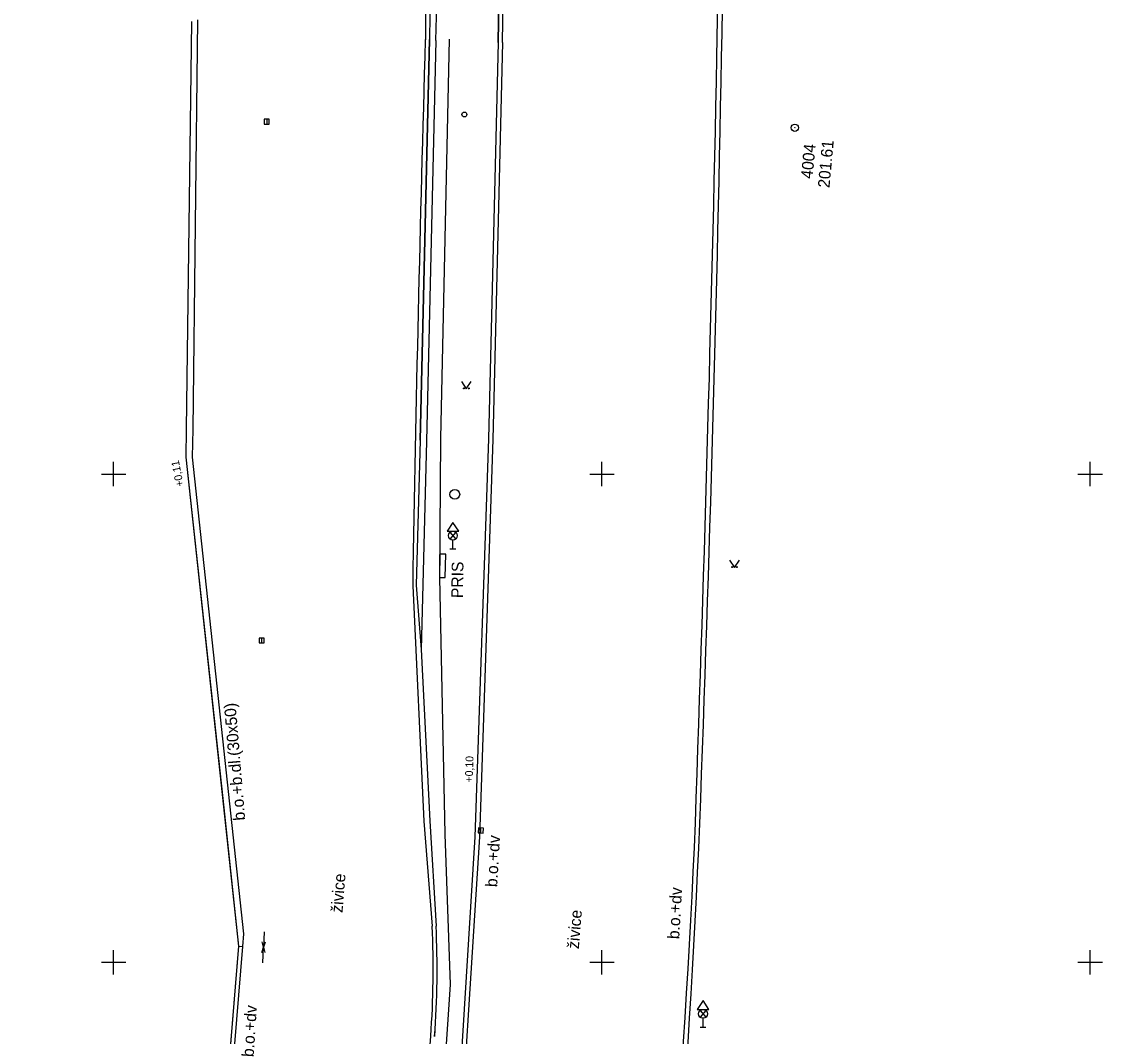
# Model space of a CAD drawing. Extents: x -599151 to -598424, y -1163476 to -1161924.
# Drawn here: x -598679.7 to -598624.4, y -1162503.8 to -1162451.8 of the extents above; entities that cross this region are included whole.
import ezdxf

# ---------------------------------------------------------------- set-up
doc = ezdxf.new("R2010")
doc.units = 0
for name, color, linetype in [('Vrstva 10', 7, 'Continuous'), ('Vrstva 14', 7, 'Continuous'), ('Vrstva 2', 7, 'Continuous'), ('Vrstva 21', 7, 'Continuous'), ('Vrstva 23', 7, 'Continuous'), ('Vrstva 25', 7, 'Continuous'), ('Vrstva 29', 7, 'Continuous'), ('Vrstva 44', 7, 'Continuous'), ('Vrstva 49', 7, 'Continuous'), ('Vrstva 50', 7, 'Continuous'), ('Vrstva 62', 7, 'Continuous'), ('Vrstva 63', 7, 'Continuous'), ('Vrstva 7', 7, 'Continuous')]:
    doc.layers.add(name, color=color, linetype=linetype)

msp = doc.modelspace()

# ---------------------------------------------------------------- linework, layer by layer
at = {"layer": 'Vrstva 10'}
msp.add_lwpolyline([(-598657.82, -1162452.73), (-598658.26, -1162473.18), (-598658.32, -1162480.293), (-598658.04, -1162493.44), (-598657.77, -1162501.13), (-598658.57, -1162513.12), (-598660.43, -1162532.68), (-598662.96, -1162552.16), (-598666.55, -1162571.73), (-598670.98, -1162591.44), (-598675.92, -1162611.16), (-598679.71, -1162624.76)], dxfattribs=at)
at = {"layer": 'Vrstva 14'}
for points in [[(-598657.193, -1162470.259), (-598656.943, -1162470.634), (-598656.693, -1162470.259)], [(-598643.462, -1162479.411), (-598643.212, -1162479.786), (-598642.962, -1162479.411)]]:
    msp.add_lwpolyline(points, dxfattribs=at)
for centre in [(-598657.068, -1162470.609), (-598656.818, -1162470.609), (-598643.337, -1162479.761), (-598643.087, -1162479.761)]:
    msp.add_circle(centre, 0.025, dxfattribs=at)
at = {"layer": 'Vrstva 2'}
for radius in [0.187, 0.00896]:
    msp.add_circle((-598640.12, -1162457.26), radius, dxfattribs=at)
at = {"layer": 'Vrstva 21'}
msp.add_lwpolyline([(-598658.5, -1162452.8), (-598658.98, -1162473.31), (-598659.26, -1162483.98), (-598658.81, -1162492.76), (-598658.491, -1162498.147)], dxfattribs=at)
for centre, radius, start, end in [((-601785.869, -1162380.888), 3128.195, 358.68275, 359.408531), ((-598705.141, -1162500.386), 46.704, 355.8125, 2.7473)]:
    msp.add_arc(centre, radius, start, end, dxfattribs=at)
at = {"layer": 'Vrstva 23'}
msp.add_circle((-598657.04, -1162456.58), 0.125, dxfattribs=at)
at = {"layer": 'Vrstva 25'}
for p, q in [((-598667.16, -1162456.825), (-598667.16, -1162457.075)), ((-598667.42, -1162483.395), (-598667.42, -1162483.645)), ((-598656.205, -1162493.375), (-598656.195, -1162493.125))]:
    msp.add_line(p, q, dxfattribs=at)
for points in [[(-598667.285, -1162456.825), (-598667.285, -1162457.075), (-598667.035, -1162457.075), (-598667.035, -1162456.825)], [(-598667.545, -1162483.395), (-598667.545, -1162483.645), (-598667.295, -1162483.645), (-598667.295, -1162483.395)], [(-598656.08, -1162493.38), (-598656.07, -1162493.13), (-598656.32, -1162493.12), (-598656.33, -1162493.37)]]:
    msp.add_lwpolyline(points, close=True, dxfattribs=at)
msp.add_circle((-598657.53, -1162476.04), 0.25, dxfattribs=at)
at = {"layer": 'Vrstva 29'}
msp.add_lwpolyline([(-598658.32, -1162480.293), (-598658.018, -1162480.3), (-598657.99, -1162479.1), (-598658.292, -1162479.093)], close=True, dxfattribs=at)
at = {"layer": 'Vrstva 44'}
for p, q in [((-598657.48, -1162477.98), (-598657.78, -1162478.324)), ((-598657.78, -1162477.98), (-598657.48, -1162478.324)), ((-598657.63, -1162478.83), (-598657.63, -1162478.38)), ((-598657.78, -1162478.83), (-598657.48, -1162478.83)), ((-598644.67, -1162502.47), (-598644.97, -1162502.814)), ((-598644.97, -1162502.47), (-598644.67, -1162502.814)), ((-598644.82, -1162503.32), (-598644.82, -1162502.87)), ((-598644.97, -1162503.32), (-598644.67, -1162503.32))]:
    msp.add_line(p, q, dxfattribs=at)
for points in [[(-598657.93, -1162477.924), (-598657.33, -1162477.924), (-598657.63, -1162477.474), (-598657.93, -1162477.924)], [(-598645.12, -1162502.414), (-598644.52, -1162502.414), (-598644.82, -1162501.964), (-598645.12, -1162502.414)]]:
    msp.add_lwpolyline(points, dxfattribs=at)
for centre in [(-598657.63, -1162478.152), (-598644.82, -1162502.642)]:
    msp.add_circle(centre, 0.228, dxfattribs=at)
at = {"layer": 'Vrstva 49'}
for p, q in [((-598667.296, -1162498.442), (-598667.327, -1162499.233)), ((-598667.409, -1162499.498), (-598667.327, -1162499.233)), ((-598667.327, -1162499.233), (-598667.39, -1162498.96)), ((-598667.357, -1162500.024), (-598667.327, -1162499.233)), ((-598667.246, -1162498.966), (-598667.327, -1162499.233)), ((-598667.327, -1162499.233), (-598667.264, -1162499.506))]:
    msp.add_line(p, q, dxfattribs=at)
at = {"layer": 'Vrstva 62'}
for p, q in [((-598675, -1162475.625), (-598675, -1162474.375)), ((-598650, -1162475.625), (-598650, -1162474.375)), ((-598625, -1162475.625), (-598625, -1162474.375)), ((-598675.625, -1162475), (-598674.375, -1162475)), ((-598650.625, -1162475), (-598649.375, -1162475)), ((-598625.625, -1162475), (-598624.375, -1162475)), ((-598675, -1162500.625), (-598675, -1162499.375)), ((-598650, -1162500.625), (-598650, -1162499.375)), ((-598625, -1162500.625), (-598625, -1162499.375)), ((-598675.625, -1162500), (-598674.375, -1162500)), ((-598650.625, -1162500), (-598649.375, -1162500)), ((-598625.625, -1162500), (-598624.375, -1162500))]:
    msp.add_line(p, q, dxfattribs=at)
at = {"layer": 'Vrstva 63'}
for points in [[(-598655.01, -1162433.67), (-598655.31, -1162452.9), (-598655.81, -1162473.2), (-598656.5, -1162493.58), (-598657.72, -1162513.16), (-598659.63, -1162532.7), (-598662.2, -1162552.27)], [(-598677, -1162549.89), (-598674.55, -1162530.94), (-598674.13, -1162527.37), (-598670.27, -1162514.94), (-598669.73, -1162513.14), (-598668.58, -1162499.17), (-598671.29, -1162474.14), (-598671.26, -1162472.7), (-598671.002, -1162451.826)], [(-598658.82, -1162452.749), (-598659.31, -1162473.26), (-598659.51, -1162480.68), (-598659.26, -1162483.98), (-598658.81, -1162492.76), (-598658.491, -1162498.147)]]:
    msp.add_lwpolyline(points, dxfattribs=at)
for centre, radius, start, end in [((-514506.267, -1163645.477), 84161.005, 179.16104444, 179.18797778), ((-602002.258, -1162387.313), 3359.044, 358.868233, 359.546325), ((-600665.364, -1162415.528), 2021.854, 357.77115, 358.919347), ((-599239.98, -1162466.516), 595.581, 353.505608, 357.339669), ((-598705.472, -1162500.383), 47.034, 355.8396, 2.7252)]:
    msp.add_arc(centre, radius, start, end, dxfattribs=at)
at = {"layer": 'Vrstva 7'}
for p, q in [((-598659.687, -1162480.718), (-598659.11, -1162492.77)), ((-598659.11, -1162492.77), (-598658.691, -1162498.156))]:
    msp.add_line(p, q, dxfattribs=at)
for points in [[(-598644.11, -1162453.65), (-598643.78, -1162434.06), (-598643.75, -1162428.05), (-598643.462, -1162428.053)], [(-598655.31, -1162452.9), (-598655.01, -1162433.67)], [(-598655.09, -1162452.9), (-598654.79, -1162433.67)], [(-598677, -1162549.89), (-598674.55, -1162530.94), (-598674.13, -1162527.37), (-598670.27, -1162514.94), (-598669.73, -1162513.14), (-598669.69, -1162512.75), (-598668.58, -1162499.17), (-598669.39, -1162491.62), (-598671.29, -1162474.14), (-598671.26, -1162472.7), (-598671.002, -1162451.826)], [(-598668.38, -1162499.186), (-598668.328, -1162498.546), (-598670.963, -1162474.131), (-598670.93, -1162472.7), (-598670.682, -1162451.734)], [(-598659.31, -1162473.26), (-598658.82, -1162452.75)], [(-598655.31, -1162452.9), (-598655.81, -1162473.2), (-598656.5, -1162493.58), (-598657.72, -1162513.16), (-598659.63, -1162532.7), (-598662.2, -1162552.27)], [(-598655.09, -1162452.9), (-598655.58, -1162473.23), (-598656.26, -1162493.58), (-598657.52, -1162513.17), (-598659.42, -1162532.73)], [(-598659.31, -1162473.26), (-598659.51, -1162480.68)], [(-598659.51, -1162480.68), (-598659.26, -1162483.98)], [(-598659.26, -1162483.98), (-598658.81, -1162492.76), (-598658.491, -1162498.147)], [(-598669.519, -1162513.11), (-598668.38, -1162499.186)], [(-598668.58, -1162499.17), (-598668.38, -1162499.186)]]:
    msp.add_lwpolyline(points, dxfattribs=at)
for centre, radius, start, end in [((-587520.198, -1162590.555), 11139.694, 179.0876056, 179.2912), ((-514506.27, -1163645.477), 84161.002, 179.16104167, 179.18797778), ((-602002.258, -1162387.313), 3359.044, 358.868233, 359.546325), ((-596517.905, -1162516.274), 2142.077, 178.300636, 179.048922), ((-601151.443, -1162402.653), 2507.851, 357.909822, 358.834806), ((-600665.364, -1162415.528), 2021.854, 357.77115, 358.919347), ((-599244.402, -1162465.655), 599.818, 353.474675, 357.279972), ((-599239.98, -1162466.516), 595.581, 353.505608, 357.339669), ((-598705.472, -1162500.383), 47.034, 355.8396, 2.7255), ((-598705.472, -1162500.383), 46.834, 355.8396, 2.7255), ((-599333.055, -1162457.651), 675.87, 353.651167, 356.086389)]:
    msp.add_arc(centre, radius, start, end, dxfattribs=at)

# ---------------------------------------------------------------- texts
at = {"layer": 'Vrstva 2'}
for s, rotation, p in [('4004', 84.5632, (-598639.22, -1162459.892)), ('201.61', 84.7088, (-598638.35, -1162460.361))]:
    msp.add_text(s, height=0.6, rotation=rotation, dxfattribs=at).set_placement(p)
at = {"layer": 'Vrstva 49'}
for s, rotation, p in [('PRIS', 89.1962, (-598657.114, -1162481.355)), ('b.o.+b.dl.(30x50)', 94.719, (-598668.26, -1162492.72)), ('b.o.+dv', 86.6099, (-598655.366, -1162496.163)), ('živice', 85.3272, (-598663.284, -1162497.479)), ('b.o.+dv', 86.6099, (-598646.046, -1162498.828)), ('živice', 85.3272, (-598651.183, -1162499.332)), ('b.o.+dv', 86.1447, (-598667.835, -1162504.867))]:
    msp.add_text(s, height=0.6, rotation=rotation, dxfattribs=at).set_placement(p)
at = {"layer": 'Vrstva 50'}
for s, rotation, p in [('+0,11', 100.9919, (-598671.406, -1162475.6)), ('+0,10', 88.2111, (-598656.616, -1162490.795))]:
    msp.add_text(s, height=0.4, rotation=rotation, dxfattribs=at).set_placement(p)

doc.saveas('drawing.dxf')
